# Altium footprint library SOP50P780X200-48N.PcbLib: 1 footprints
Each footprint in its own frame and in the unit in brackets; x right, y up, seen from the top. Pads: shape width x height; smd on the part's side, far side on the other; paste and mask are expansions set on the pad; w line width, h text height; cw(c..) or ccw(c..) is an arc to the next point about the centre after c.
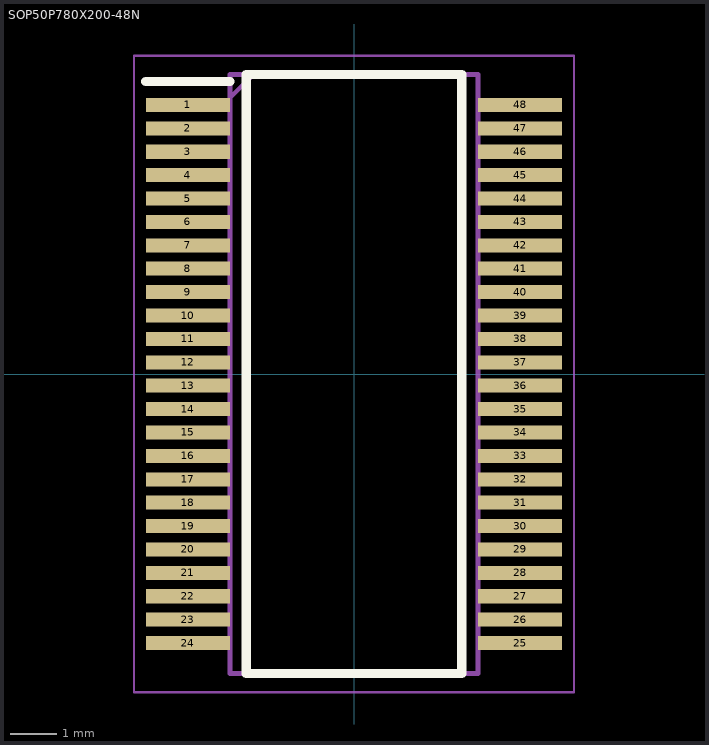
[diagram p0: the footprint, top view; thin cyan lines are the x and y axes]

## SOP50P780X200-48N [mm]
pads (48):
  rect 1.8x0.3 smd: 1(-3.55,5.75) 2(-3.55,5.25) 3(-3.55,4.75) 4(-3.55,4.25) 5(-3.55,3.75) 6(-3.55,3.25) 7(-3.55,2.75) 8(-3.55,2.25) 9(-3.55,1.75) 10(-3.55,1.25) 11(-3.55,0.75) 12(-3.55,0.25) 13(-3.55,-0.25) 14(-3.55,-0.75) 15(-3.55,-1.25) 16(-3.55,-1.75) 17(-3.55,-2.25) 18(-3.55,-2.75) 19(-3.55,-3.25) 20(-3.55,-3.75) 21(-3.55,-4.25) 22(-3.55,-4.75) 23(-3.55,-5.25) 24(-3.55,-5.75) 25(3.55,-5.75) 26(3.55,-5.25) 27(3.55,-4.75) 28(3.55,-4.25) 29(3.55,-3.75) 30(3.55,-3.25) 31(3.55,-2.75) 32(3.55,-2.25) 33(3.55,-1.75) 34(3.55,-1.25) 35(3.55,-0.75) 36(3.55,-0.25) 37(3.55,0.25) 38(3.55,0.75) 39(3.55,1.25) 40(3.55,1.75) 41(3.55,2.25) 42(3.55,2.75) 43(3.55,3.25) 44(3.55,3.75) 45(3.55,4.25) 46(3.55,4.75) 47(3.55,5.25) 48(3.55,5.75)
Top Overlay:
  lines w0.2: -4.45,6.25 -2.65,6.25 ; -2.3,-6.4 2.3,-6.4 2.3,6.4 -2.3,6.4 -2.3,-6.4
Mechanical 15:
  lines w0.1: -2.65,5.9 -2.15,6.4 ; -2.65,-6.4 2.65,-6.4 2.65,6.4 -2.65,6.4 -2.65,-6.4
Mechanical 20:
  lines w0.05: -4.7,-6.8 4.7,-6.8 4.7,6.8 -4.7,6.8 -4.7,-6.8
